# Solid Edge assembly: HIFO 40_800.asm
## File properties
Title: Zylinder
Author: ahadarics
Template: iso assembly.asm
Last saved by: ahadarics
Revision: 60
Application: Solid Edge
Username: ahadarics
Dokumentum tartalom típus: 1
Document Number: HIFO 40/800
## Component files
Profilrohr 40_800.par
Mutter.par
Kolbenstange 40_800.par
Kit_1.par
Kit_2.par
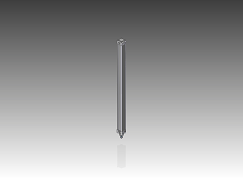
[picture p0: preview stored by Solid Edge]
